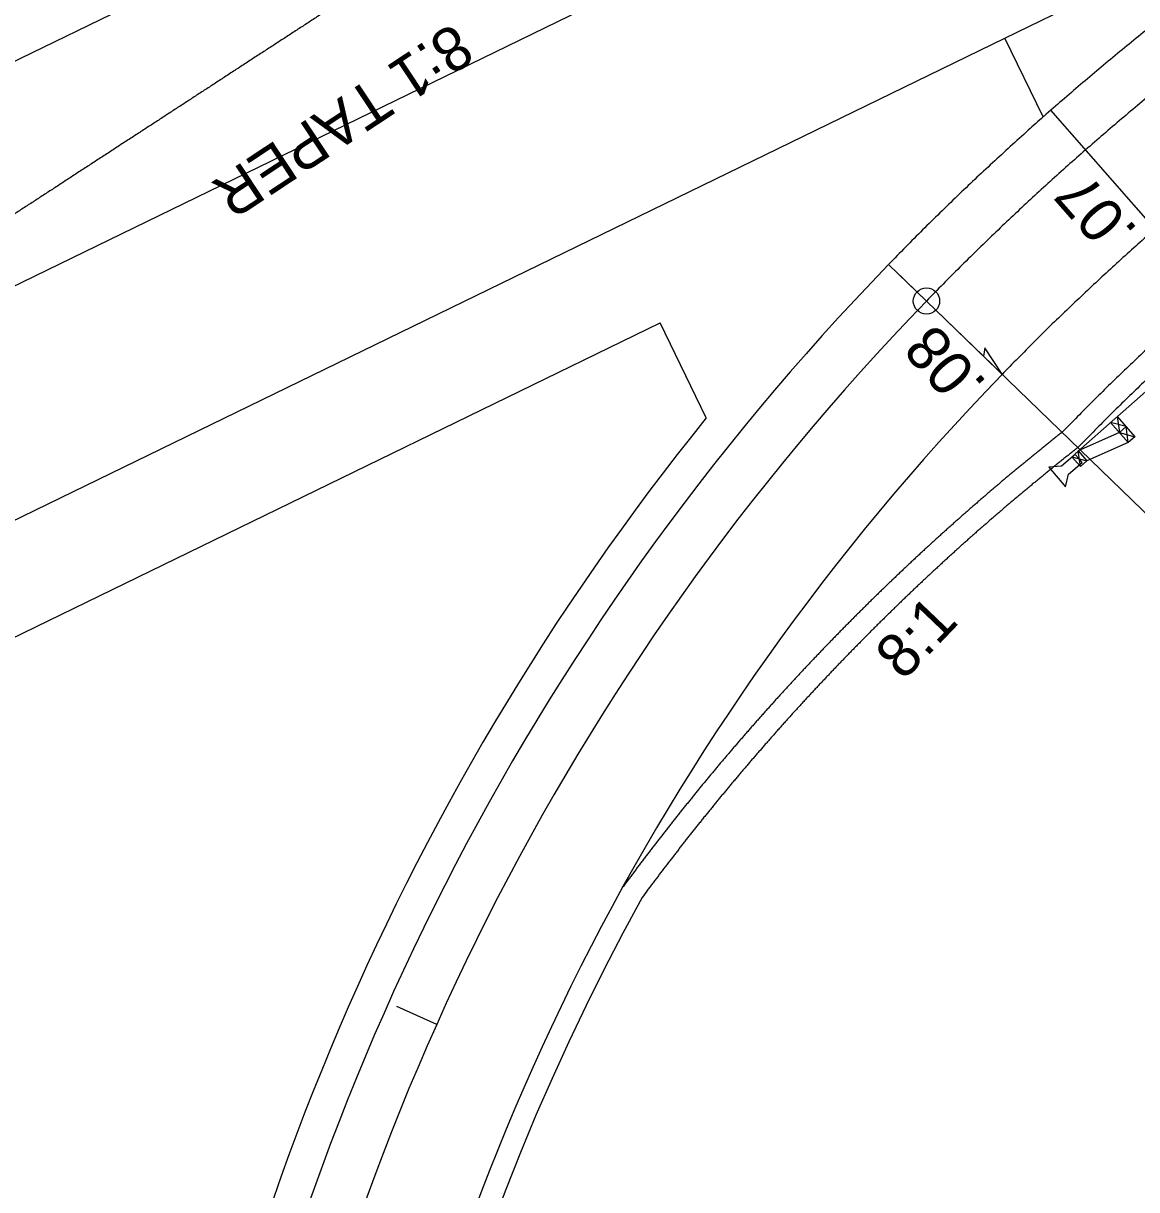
# Model space of a CAD drawing. Extents: x 2389694 to 2405615, y 547005 to 573532.
# Drawn here: x 2402110.3 to 2402237.1, y 570674.4 to 570807.3 of the extents above; entities that cross this region are included whole.
import ezdxf

# ---------------------------------------------------------------- set-up
doc = ezdxf.new("R2010")
doc.units = 0
for name, color, linetype in [('Prop Cable Guiderail Single Face', 7, 'Continuous'), ('Prop Conc 2ft 6in Curb and Gutter', 7, 'Continuous'), ('Prop Dimension Text', 7, 'Continuous'), ('Prop EOT', 7, 'Continuous'), ('Prop GRAU 350 Approach CELL', 7, 'Continuous'), ('Prop Horizontal Alignment', 7, 'Continuous'), ('Prop Horizontal Alignment Curve and Spiral Data', 7, 'Continuous'), ('Prop Horizontal Alignment Tick Small', 7, 'Continuous'), ('Prop Lane Lines', 7, 'Continuous'), ('Prop Super Arrow 1 Lane CELL', 7, 'Continuous'), ('Prop Superelevation Label', 7, 'Continuous')]:
    doc.layers.add(name, color=color, linetype=linetype)

msp = doc.modelspace()

# ---------------------------------------------------------------- linework, layer by layer
at = {"layer": 'Prop Cable Guiderail Single Face'}
msp.add_spline([(2402134.47, 570827.8), (2402133.78, 570827.41), (2402133.09, 570827.02), (2402132.4, 570826.63), (2402131.72, 570826.24), (2402131.03, 570825.85), (2402130.34, 570825.46), (2402129.66, 570825.07), (2402128.97, 570824.68), (2402128.29, 570824.3), (2402127.6, 570823.91), (2402126.91, 570823.52), (2402126.22, 570823.13), (2402125.54, 570822.74), (2402124.85, 570822.35), (2402124.16, 570821.96), (2402123.48, 570821.57), (2402122.79, 570821.18), (2402122.11, 570820.8), (2402121.42, 570820.41), (2402120.73, 570820.02), (2402120.04, 570819.63), (2402119.36, 570819.24), (2402118.67, 570818.85), (2402117.98, 570818.46), (2402117.29, 570818.07), (2402116.61, 570817.69), (2402115.93, 570817.3), (2402115.24, 570816.91), (2402114.55, 570816.52), (2402113.86, 570816.13), (2402113.18, 570815.74), (2402112.49, 570815.35), (2402111.8, 570814.96), (2402111.11, 570814.57), (2402110.43, 570814.19), (2402109.74, 570813.8), (2402109.06, 570813.41), (2402108.37, 570813.02), (2402107.68, 570812.63), (2402107, 570812.24), (2402106.31, 570811.85), (2402105.62, 570811.46), (2402104.93, 570811.07), (2402104.25, 570810.68), (2402103.56, 570810.29), (2402102.87, 570809.9), (2402102.19, 570809.51), (2402101.5, 570809.12), (2402100.82, 570808.74), (2402100.13, 570808.35), (2402099.44, 570807.96), (2402098.75, 570807.57), (2402098.07, 570807.18), (2402097.38, 570806.79), (2402096.69, 570806.4), (2402096.01, 570806.01), (2402095.33, 570805.63), (2402094.64, 570805.24), (2402093.95, 570804.85), (2402093.26, 570804.46), (2402092.57, 570804.07), (2402091.89, 570803.68), (2402091.2, 570803.29), (2402090.51, 570802.9), (2402089.82, 570802.51), (2402089.14, 570802.13), (2402088.46, 570801.74), (2402087.77, 570801.35), (2402087.08, 570800.96), (2402086.39, 570800.57), (2402085.71, 570800.18), (2402085.02, 570799.79), (2402084.33, 570799.4), (2402083.64, 570799.01)], degree=3, dxfattribs=at)
at = {"layer": 'Prop Conc 2ft 6in Curb and Gutter'}
msp.add_arc((2402419.3, 570575.99), 272.5, 151.0902, 272.8811, dxfattribs=at)
for points in [[(2402276.54, 570797.84), (2402276.44, 570797.77), (2402274.36, 570796.3), (2402272.29, 570794.81), (2402270.23, 570793.32), (2402268.19, 570791.81), (2402266.16, 570790.29), (2402264.14, 570788.76), (2402262.13, 570787.22), (2402260.14, 570785.66), (2402258.16, 570784.1), (2402256.2, 570782.51), (2402254.25, 570780.92), (2402252.32, 570779.31), (2402250.4, 570777.69), (2402248.5, 570776.06), (2402246.61, 570774.41), (2402244.74, 570772.75), (2402242.88, 570771.07), (2402241.04, 570769.38), (2402239.22, 570767.68), (2402237.42, 570765.96), (2402235.63, 570764.23), (2402233.86, 570762.49), (2402232.11, 570760.73), (2402230.3, 570758.88)], [(2402230.38, 570758.96), (2402230, 570758.67), (2402229.63, 570758.37), (2402229.26, 570758.08), (2402228.89, 570757.78), (2402228.52, 570757.48), (2402228.14, 570757.19), (2402227.77, 570756.89), (2402227.4, 570756.59), (2402227.03, 570756.29), (2402226.66, 570755.99), (2402226.3, 570755.69), (2402225.93, 570755.38), (2402225.56, 570755.08), (2402225.19, 570754.78), (2402224.83, 570754.47), (2402224.46, 570754.17), (2402224.09, 570753.86), (2402223.73, 570753.56), (2402223.36, 570753.25), (2402223, 570752.94), (2402222.63, 570752.63), (2402222.27, 570752.32), (2402221.91, 570752.01), (2402221.55, 570751.7), (2402221.18, 570751.39), (2402220.82, 570751.08), (2402220.46, 570750.77), (2402220.1, 570750.45), (2402219.74, 570750.14), (2402219.38, 570749.82), (2402219.02, 570749.51), (2402218.66, 570749.19), (2402218.3, 570748.87), (2402217.95, 570748.56), (2402217.59, 570748.24), (2402217.23, 570747.92), (2402216.88, 570747.6), (2402216.52, 570747.28), (2402216.16, 570746.95), (2402215.81, 570746.63), (2402215.46, 570746.31), (2402215.1, 570745.98), (2402214.75, 570745.66), (2402214.4, 570745.33), (2402214.04, 570745.01), (2402213.69, 570744.68), (2402213.34, 570744.35), (2402212.99, 570744.03), (2402212.64, 570743.7), (2402212.29, 570743.37), (2402211.94, 570743.04), (2402211.59, 570742.7), (2402211.24, 570742.37), (2402210.9, 570742.04), (2402210.55, 570741.71), (2402210.2, 570741.37), (2402209.86, 570741.04), (2402209.51, 570740.7), (2402209.17, 570740.37), (2402208.82, 570740.03), (2402208.48, 570739.69), (2402208.14, 570739.35), (2402207.79, 570739.02), (2402207.45, 570738.68), (2402207.11, 570738.34), (2402206.77, 570738), (2402206.43, 570737.65), (2402206.09, 570737.31), (2402205.75, 570736.97), (2402205.41, 570736.62), (2402205.07, 570736.28), (2402204.73, 570735.93), (2402204.39, 570735.59), (2402204.06, 570735.24)], [(2402204.06, 570735.24), (2402203.72, 570734.89), (2402203.39, 570734.55), (2402203.05, 570734.2), (2402202.72, 570733.85), (2402202.38, 570733.5), (2402202.05, 570733.15), (2402201.72, 570732.8), (2402201.38, 570732.44), (2402201.05, 570732.09), (2402200.72, 570731.74), (2402200.39, 570731.38), (2402200.06, 570731.03), (2402199.73, 570730.67), (2402199.4, 570730.32), (2402199.07, 570729.96), (2402198.74, 570729.6), (2402198.42, 570729.24), (2402198.09, 570728.89), (2402197.76, 570728.53), (2402197.44, 570728.17), (2402197.11, 570727.8), (2402196.79, 570727.44), (2402196.47, 570727.08), (2402196.14, 570726.72), (2402195.82, 570726.35), (2402195.5, 570725.99), (2402195.18, 570725.62), (2402194.86, 570725.26), (2402194.54, 570724.89), (2402194.22, 570724.52), (2402193.9, 570724.16), (2402193.58, 570723.79), (2402193.26, 570723.42), (2402192.94, 570723.05), (2402192.63, 570722.68), (2402192.31, 570722.31), (2402192, 570721.94), (2402191.68, 570721.56), (2402191.37, 570721.19), (2402191.05, 570720.82), (2402190.74, 570720.44), (2402190.43, 570720.07), (2402190.12, 570719.69), (2402189.8, 570719.32), (2402189.49, 570718.94), (2402189.18, 570718.56), (2402188.87, 570718.18), (2402188.57, 570717.8), (2402188.26, 570717.43), (2402187.95, 570717.05), (2402187.64, 570716.66), (2402187.34, 570716.28), (2402187.03, 570715.9), (2402186.73, 570715.52), (2402186.42, 570715.13), (2402186.12, 570714.75), (2402185.82, 570714.37), (2402185.51, 570713.98), (2402185.21, 570713.59), (2402184.91, 570713.21), (2402184.61, 570712.82), (2402184.31, 570712.43), (2402184.01, 570712.04), (2402183.71, 570711.65), (2402183.41, 570711.26), (2402183.12, 570710.87), (2402182.82, 570710.48), (2402182.52, 570710.09), (2402182.23, 570709.7), (2402181.93, 570709.31), (2402181.64, 570708.91), (2402181.34, 570708.52), (2402180.76, 570707.73)]]:
    msp.add_spline(points, degree=3, dxfattribs=at)
at = {"layer": 'Prop EOT'}
for p, q in [((2401949.14, 570699.46), (2403805.68, 571603.12)), ((2401959.65, 570677.88), (2402222.06, 570805.61)), ((2402226.44, 570796.62), (2402222.06, 570805.61)), ((2401964.9, 570667.09), (2402182.81, 570773.16)), ((2402188.06, 570762.37), (2402182.81, 570773.16))]:
    msp.add_line(p, q, dxfattribs=at)
for radius, start, end in [(293, 135.9178, 271.0318), (275, 135.9178, 272.8811), (297, 141.132, 269.5038)]:
    msp.add_arc((2402419.3, 570575.99), radius, start, end, dxfattribs=at)
for points in [[(2402385.97, 570872.05), (2402383.54, 570870.86), (2402381.11, 570869.68), (2402378.69, 570868.5), (2402376.26, 570867.32), (2402373.84, 570866.13), (2402371.42, 570864.95), (2402369, 570863.76), (2402366.58, 570862.58), (2402364.17, 570861.39), (2402361.76, 570860.2), (2402359.35, 570859.01), (2402356.95, 570857.81), (2402354.55, 570856.61), (2402352.15, 570855.41), (2402349.76, 570854.21), (2402347.37, 570853), (2402344.98, 570851.78), (2402342.6, 570850.57), (2402340.22, 570849.34), (2402337.84, 570848.11), (2402335.47, 570846.88), (2402333.11, 570845.64), (2402330.75, 570844.4), (2402328.39, 570843.15), (2402326.04, 570841.89), (2402323.7, 570840.63), (2402321.36, 570839.36), (2402319.02, 570838.08), (2402316.7, 570836.79), (2402314.38, 570835.5), (2402312.06, 570834.2), (2402309.75, 570832.89), (2402307.45, 570831.57), (2402305.15, 570830.24), (2402302.87, 570828.9), (2402300.58, 570827.56), (2402298.31, 570826.2), (2402296.05, 570824.84), (2402293.79, 570823.46), (2402291.54, 570822.07), (2402289.3, 570820.68), (2402287.06, 570819.27), (2402284.84, 570817.85), (2402282.63, 570816.42), (2402280.42, 570814.98), (2402278.23, 570813.53), (2402276.04, 570812.06), (2402273.86, 570810.58), (2402271.7, 570809.09), (2402269.54, 570807.59), (2402267.4, 570806.07), (2402265.27, 570804.55), (2402263.14, 570803), (2402261.03, 570801.45), (2402258.94, 570799.88), (2402256.85, 570798.3), (2402254.78, 570796.7), (2402252.72, 570795.09), (2402250.67, 570793.47), (2402248.64, 570791.83), (2402246.62, 570790.18), (2402244.61, 570788.51), (2402242.62, 570786.83), (2402240.64, 570785.13), (2402238.68, 570783.42), (2402236.73, 570781.69), (2402234.8, 570779.94), (2402232.89, 570778.19), (2402230.99, 570776.41), (2402229.11, 570774.62), (2402227.24, 570772.82), (2402225.4, 570771), (2402223.57, 570769.16), (2402221.72, 570767.27)], [(2402171.98, 570826.43), (2402171.41, 570826.06), (2402170.82, 570825.68), (2402170.25, 570825.31), (2402169.68, 570824.93), (2402169.09, 570824.55), (2402168.52, 570824.18), (2402167.94, 570823.8), (2402167.36, 570823.42), (2402166.79, 570823.05), (2402166.21, 570822.68), (2402165.63, 570822.3), (2402165.06, 570821.92), (2402164.48, 570821.55), (2402163.9, 570821.17), (2402163.32, 570820.8), (2402162.75, 570820.42), (2402162.17, 570820.04), (2402161.59, 570819.67), (2402161.02, 570819.29), (2402160.45, 570818.92), (2402159.86, 570818.54), (2402159.29, 570818.17), (2402158.71, 570817.79), (2402158.13, 570817.41), (2402157.56, 570817.04), (2402156.98, 570816.66), (2402156.4, 570816.28), (2402155.83, 570815.91), (2402155.25, 570815.54), (2402154.67, 570815.16), (2402154.1, 570814.78), (2402153.52, 570814.41), (2402152.94, 570814.03), (2402152.36, 570813.66), (2402151.79, 570813.28), (2402151.21, 570812.9), (2402150.63, 570812.53), (2402150.06, 570812.15), (2402149.48, 570811.77), (2402148.9, 570811.4), (2402148.33, 570811.03), (2402147.74, 570810.65), (2402147.17, 570810.27), (2402146.6, 570809.9), (2402146.01, 570809.52), (2402145.44, 570809.15), (2402144.87, 570808.77), (2402144.28, 570808.39), (2402143.71, 570808.02), (2402143.13, 570807.64), (2402142.55, 570807.26), (2402141.98, 570806.89), (2402141.4, 570806.52), (2402140.82, 570806.14), (2402140.25, 570805.76), (2402139.67, 570805.39), (2402139.1, 570805.01), (2402138.52, 570804.63), (2402137.94, 570804.26), (2402137.37, 570803.89), (2402136.78, 570803.51), (2402136.21, 570803.13), (2402135.64, 570802.76), (2402135.05, 570802.38), (2402134.48, 570802.01), (2402133.9, 570801.63), (2402133.32, 570801.25), (2402132.75, 570800.88), (2402132.17, 570800.5), (2402131.59, 570800.12), (2402131.02, 570799.75), (2402130.44, 570799.38), (2402129.86, 570799), (2402129.29, 570798.62)], [(2402275.11, 570799.89), (2402275, 570799.81), (2402272.91, 570798.33), (2402270.82, 570796.84), (2402268.75, 570795.34), (2402266.7, 570793.82), (2402264.65, 570792.29), (2402262.62, 570790.75), (2402260.6, 570789.2), (2402258.59, 570787.63), (2402256.6, 570786.05), (2402254.62, 570784.45), (2402252.66, 570782.85), (2402250.71, 570781.23), (2402248.78, 570779.59), (2402246.86, 570777.95), (2402244.96, 570776.28), (2402243.07, 570774.61), (2402241.2, 570772.92), (2402239.34, 570771.22), (2402237.51, 570769.5), (2402235.69, 570767.77), (2402233.88, 570766.02), (2402232.1, 570764.26), (2402230.33, 570762.49), (2402228.51, 570760.63)], [(2402129.29, 570798.62), (2402128.71, 570798.25), (2402128.13, 570797.87), (2402127.55, 570797.5), (2402126.98, 570797.12), (2402126.4, 570796.74), (2402125.82, 570796.37), (2402125.25, 570795.99), (2402124.67, 570795.61), (2402124.09, 570795.24), (2402123.52, 570794.87), (2402122.94, 570794.49), (2402122.36, 570794.11), (2402121.79, 570793.74), (2402121.2, 570793.36), (2402120.63, 570792.98), (2402120.06, 570792.61), (2402119.47, 570792.23), (2402118.9, 570791.86), (2402118.32, 570791.48), (2402117.75, 570791.11), (2402117.17, 570790.73), (2402116.59, 570790.36), (2402116.02, 570789.98), (2402115.44, 570789.6), (2402114.86, 570789.23), (2402114.29, 570788.85), (2402113.71, 570788.47), (2402113.13, 570788.1), (2402112.56, 570787.73), (2402111.97, 570787.35), (2402111.4, 570786.97), (2402110.83, 570786.6), (2402110.24, 570786.22), (2402109.67, 570785.85), (2402109.1, 570785.47), (2402108.51, 570785.09), (2402107.94, 570784.72), (2402107.36, 570784.34), (2402106.78, 570783.96), (2402106.21, 570783.59), (2402105.63, 570783.22), (2402105.05, 570782.84), (2402104.48, 570782.46), (2402103.9, 570782.09), (2402103.32, 570781.71), (2402102.74, 570781.33), (2402102.17, 570780.96), (2402101.59, 570780.58), (2402101.01, 570780.21), (2402100.44, 570779.83), (2402099.86, 570779.45), (2402099.28, 570779.08), (2402098.71, 570778.71), (2402098.13, 570778.33), (2402097.55, 570777.95), (2402096.98, 570777.58), (2402096.4, 570777.2), (2402095.82, 570776.82), (2402095.25, 570776.45), (2402094.67, 570776.08), (2402094.09, 570775.7), (2402093.52, 570775.32), (2402092.94, 570774.95), (2402092.36, 570774.57), (2402091.78, 570774.2), (2402091.21, 570773.82), (2402090.63, 570773.44), (2402090.05, 570773.07), (2402089.48, 570772.69), (2402088.9, 570772.31), (2402088.32, 570771.94), (2402087.75, 570771.57), (2402086.59, 570770.81)], [(2402226.44, 570796.62), (2402224.73, 570795.1), (2402222.68, 570793.25), (2402220.66, 570791.39), (2402218.64, 570789.51), (2402216.65, 570787.61), (2402214.67, 570785.69), (2402212.7, 570783.76), (2402210.76, 570781.8), (2402208.85, 570779.85)], [(2402228.58, 570760.7), (2402228.2, 570760.4), (2402227.83, 570760.1), (2402227.45, 570759.81), (2402227.08, 570759.51), (2402226.7, 570759.21), (2402226.33, 570758.91), (2402225.96, 570758.6), (2402225.58, 570758.3), (2402225.21, 570758), (2402224.84, 570757.69), (2402224.47, 570757.39), (2402224.1, 570757.09), (2402223.72, 570756.78), (2402223.35, 570756.47), (2402222.98, 570756.17), (2402222.61, 570755.86), (2402222.25, 570755.55), (2402221.88, 570755.24), (2402221.51, 570754.93), (2402221.14, 570754.62), (2402220.77, 570754.3), (2402220.41, 570753.99), (2402220.04, 570753.68), (2402219.68, 570753.36), (2402219.31, 570753.05), (2402218.95, 570752.73), (2402218.58, 570752.42), (2402218.22, 570752.1), (2402217.86, 570751.78), (2402217.49, 570751.46), (2402217.13, 570751.14), (2402216.77, 570750.82), (2402216.41, 570750.5), (2402216.05, 570750.18), (2402215.69, 570749.86), (2402215.33, 570749.54), (2402214.97, 570749.21), (2402214.61, 570748.89), (2402214.25, 570748.56), (2402213.89, 570748.24), (2402213.54, 570747.91), (2402213.18, 570747.58), (2402212.82, 570747.26), (2402212.47, 570746.93), (2402212.11, 570746.6), (2402211.76, 570746.27), (2402211.41, 570745.94), (2402211.05, 570745.6), (2402210.7, 570745.27), (2402210.35, 570744.94), (2402209.99, 570744.6), (2402209.64, 570744.27), (2402209.29, 570743.93), (2402208.94, 570743.6), (2402208.59, 570743.26), (2402208.24, 570742.92), (2402207.89, 570742.59), (2402207.55, 570742.25), (2402207.2, 570741.91), (2402206.85, 570741.57), (2402206.5, 570741.23), (2402206.16, 570740.88), (2402205.81, 570740.54), (2402205.47, 570740.2), (2402205.12, 570739.86), (2402204.78, 570739.51), (2402204.44, 570739.17), (2402204.09, 570738.82), (2402203.75, 570738.47), (2402203.41, 570738.13), (2402203.07, 570737.78), (2402202.73, 570737.43), (2402202.39, 570737.08), (2402202.05, 570736.73)], [(2402202.05, 570736.73), (2402201.71, 570736.38), (2402201.37, 570736.03), (2402201.03, 570735.67), (2402200.7, 570735.32), (2402200.36, 570734.97), (2402200.02, 570734.61), (2402199.69, 570734.26), (2402199.35, 570733.9), (2402199.02, 570733.55), (2402198.68, 570733.19), (2402198.35, 570732.83), (2402198.02, 570732.47), (2402197.69, 570732.11), (2402197.35, 570731.75), (2402197.02, 570731.39), (2402196.69, 570731.03), (2402196.36, 570730.67), (2402196.03, 570730.31), (2402195.71, 570729.94), (2402195.38, 570729.58), (2402195.05, 570729.21), (2402194.72, 570728.85), (2402194.4, 570728.48), (2402194.07, 570728.12), (2402193.75, 570727.75), (2402193.42, 570727.38), (2402193.1, 570727.01), (2402192.77, 570726.64), (2402192.45, 570726.27), (2402192.13, 570725.9), (2402191.81, 570725.53), (2402191.49, 570725.16), (2402191.17, 570724.79), (2402190.85, 570724.41), (2402190.53, 570724.04), (2402190.21, 570723.66), (2402189.89, 570723.29), (2402189.57, 570722.91), (2402189.26, 570722.53), (2402188.94, 570722.16), (2402188.63, 570721.78), (2402188.31, 570721.4), (2402188, 570721.02), (2402187.68, 570720.64), (2402187.37, 570720.26), (2402187.06, 570719.88), (2402186.75, 570719.5), (2402186.44, 570719.11), (2402186.13, 570718.73), (2402185.82, 570718.35), (2402185.51, 570717.96), (2402185.2, 570717.58), (2402184.89, 570717.19), (2402184.58, 570716.8), (2402184.28, 570716.42), (2402183.97, 570716.03), (2402183.66, 570715.64), (2402183.36, 570715.25), (2402183.06, 570714.86), (2402182.75, 570714.47), (2402182.45, 570714.08), (2402182.15, 570713.69), (2402181.85, 570713.3), (2402181.54, 570712.9), (2402181.24, 570712.51), (2402180.94, 570712.11), (2402180.65, 570711.72), (2402180.35, 570711.32), (2402180.05, 570710.93), (2402179.75, 570710.53), (2402179.46, 570710.13), (2402179.16, 570709.73), (2402178.57, 570708.94)]]:
    msp.add_spline(points, degree=3, dxfattribs=at)
at = {"layer": 'Prop GRAU 350 Approach CELL'}
for p, q in [((2402267.56, 570791.35), (2402230.06, 570758.26)), ((2402234.86, 570762.5), (2402236.88, 570760.2)), ((2402234.86, 570762.5), (2402235.12, 570760.69)), ((2402234.11, 570761.84), (2402236.13, 570759.54)), ((2402235.87, 570761.35), (2402234.11, 570761.84)), ((2402235.87, 570761.35), (2402235.12, 570760.69)), ((2402236.13, 570759.54), (2402235.87, 570761.35)), ((2402235.12, 570760.69), (2402230.43, 570758.59)), ((2402236.13, 570759.54), (2402231.42, 570757.47)), ((2402235.12, 570760.69), (2402236.88, 570760.2)), ((2402236.88, 570760.2), (2402236.13, 570759.54)), ((2402230.08, 570758.19), (2402228.52, 570756.86)), ((2402230.48, 570757.72), (2402230.08, 570758.19)), ((2402230.43, 570758.59), (2402231.42, 570757.47)), ((2402230.67, 570756.81), (2402230.43, 570758.59)), ((2402228.52, 570756.86), (2402227.07, 570756.75)), ((2402227.07, 570756.75), (2402228.97, 570754.51)), ((2402229.32, 570755.93), (2402230.87, 570757.26)), ((2402229.68, 570757.93), (2402230.67, 570756.81)), ((2402229.68, 570757.93), (2402231.42, 570757.47)), ((2402230.87, 570757.26), (2402230.48, 570757.72)), ((2402231.42, 570757.47), (2402230.67, 570756.81)), ((2402231.42, 570757.47), (2402231.05, 570757.14)), ((2402228.97, 570754.51), (2402229.32, 570755.93))]:
    msp.add_line(p, q, dxfattribs=at)
at = {"layer": 'Prop Horizontal Alignment'}
msp.add_line((2401939.08, 570720.14), (2404036.59, 571741.09), dxfattribs=at)
msp.add_arc((2402419.3, 570575.99), 287, 135.9178, 272.8811, dxfattribs=at)
msp.add_spline([(2402380.72, 570882.83), (2402378.29, 570881.65), (2402375.86, 570880.47), (2402373.43, 570879.29), (2402371, 570878.1), (2402368.57, 570876.91), (2402366.14, 570875.73), (2402363.71, 570874.54), (2402361.29, 570873.35), (2402358.86, 570872.15), (2402356.44, 570870.96), (2402354.02, 570869.76), (2402351.6, 570868.55), (2402349.18, 570867.34), (2402346.76, 570866.13), (2402344.35, 570864.92), (2402341.94, 570863.7), (2402339.53, 570862.47), (2402337.12, 570861.24), (2402334.72, 570860.01), (2402332.32, 570858.77), (2402329.92, 570857.52), (2402327.53, 570856.27), (2402325.14, 570855.01), (2402322.75, 570853.74), (2402320.37, 570852.46), (2402317.99, 570851.18), (2402315.61, 570849.89), (2402313.24, 570848.59), (2402310.88, 570847.29), (2402308.51, 570845.97), (2402306.16, 570844.65), (2402303.81, 570843.31), (2402301.46, 570841.97), (2402299.12, 570840.62), (2402296.79, 570839.25), (2402294.46, 570837.88), (2402292.14, 570836.49), (2402289.83, 570835.1), (2402287.52, 570833.69), (2402285.22, 570832.27), (2402282.92, 570830.84), (2402280.64, 570829.4), (2402278.36, 570827.95), (2402276.09, 570826.48), (2402273.83, 570825), (2402271.57, 570823.51), (2402269.33, 570822.01), (2402267.09, 570820.49), (2402264.87, 570818.96), (2402262.65, 570817.41), (2402260.44, 570815.85), (2402258.24, 570814.28), (2402256.06, 570812.69), (2402253.88, 570811.08), (2402251.72, 570809.47), (2402249.56, 570807.83), (2402247.42, 570806.18), (2402245.29, 570804.52), (2402243.18, 570802.84), (2402241.07, 570801.14), (2402238.98, 570799.43), (2402236.9, 570797.7), (2402234.84, 570795.96), (2402232.79, 570794.2), (2402230.75, 570792.42), (2402228.73, 570790.63), (2402226.72, 570788.82), (2402224.73, 570786.99), (2402222.76, 570785.14), (2402220.8, 570783.28), (2402218.86, 570781.4), (2402216.93, 570779.5), (2402215.03, 570777.59), (2402213.14, 570775.66)], degree=3, dxfattribs=at)
at = {"layer": 'Prop Horizontal Alignment Curve and Spiral Data'}
msp.add_line((2402214.21, 570774.61), (2402298.73, 570692.76), dxfattribs=at)
msp.add_circle((2402213.14, 570775.66), 1.5, dxfattribs=at)
at = {"layer": 'Prop Horizontal Alignment Tick Small'}
for p, q in [((2402213.14, 570775.66), (2402209.55, 570779.13)), ((2402157.36, 570693.27), (2402152.79, 570695.31))]:
    msp.add_line(p, q, dxfattribs=at)
at = {"layer": 'Prop Lane Lines'}
msp.add_line((2402222.06, 570805.61), (2402420.86, 570902.38), dxfattribs=at)
msp.add_spline([(2402264.57, 570826.03), (2402263.71, 570825.44), (2402261.45, 570823.89), (2402259.2, 570822.32), (2402256.96, 570820.74), (2402254.73, 570819.14), (2402252.51, 570817.53), (2402250.31, 570815.9), (2402248.11, 570814.26), (2402245.92, 570812.6), (2402243.75, 570810.93), (2402241.58, 570809.23), (2402239.43, 570807.53), (2402237.29, 570805.8), (2402235.16, 570804.06), (2402233.05, 570802.3), (2402230.95, 570800.53), (2402228.86, 570798.74), (2402226.79, 570796.93), (2402226.44, 570796.62)], degree=3, dxfattribs=at)
at = {"layer": 'Prop Super Arrow 1 Lane CELL'}
for p, q in [((2402239.17, 570783.84), (2402227.3, 570797.38)), ((2402221.76, 570767.31), (2402208.83, 570779.83))]:
    msp.add_line(p, q, dxfattribs=at)
msp.add_lwpolyline([(2402221.76, 570767.31), (2402219.8, 570770.32), (2402219.64, 570769.36)], close=True, dxfattribs=at)

# ---------------------------------------------------------------- texts
at = {"layer": 'Prop Dimension Text'}
for s, rotation, p in [('8:1 TAPER', 213.5298, (2402159.26, 570807.46)), ('8:1', 46.304, (2402210.51, 570732.3))]:
    msp.add_text(s, height=5, rotation=rotation, dxfattribs=at).set_placement(p)
at = {"layer": 'Prop Superelevation Label'}
for s, p in [('.07', (2402237.34, 570783.75)), ('.08', (2402220.16, 570766.31))]:
    msp.add_text(s, height=5, rotation=131.2388, dxfattribs=at).set_placement(p)

doc.saveas('drawing.dxf')
